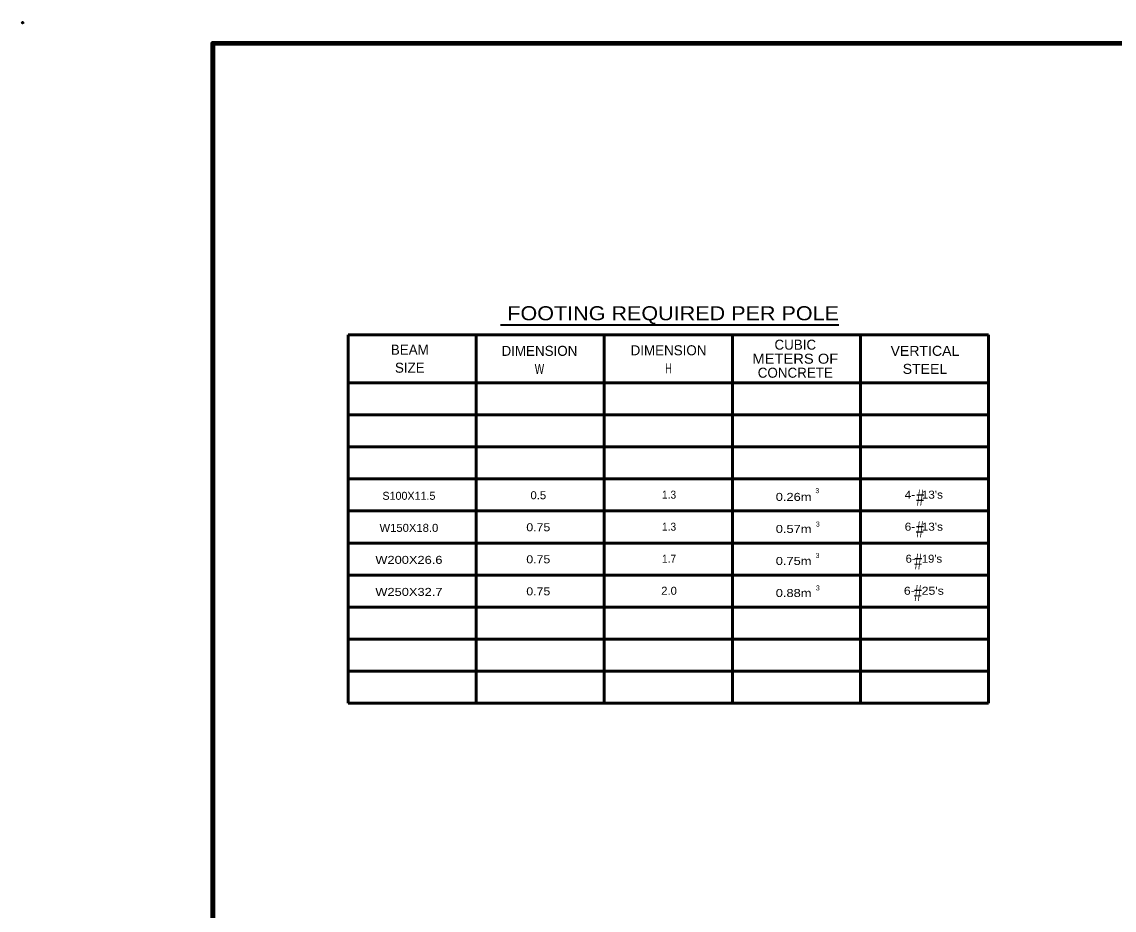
# Model space of a CAD drawing. Extents: x -27 to 828, y -12 to 532.
# Drawn here: x -27 to 300.5, y 265.3 to 531.5 of the extents above; entities that cross this region are included whole.
import ezdxf
from ezdxf.enums import TextEntityAlignment as Align

# ---------------------------------------------------------------- set-up
doc = ezdxf.new("R2010")
doc.units = 0
doc.header["$LTSCALE"] = 0.96
doc.header["$PDMODE"] = 32
doc.header["$PDSIZE"] = 0.48
doc.layers.add('1', color=7, linetype='Continuous', lineweight=35)

msp = doc.modelspace()

# ---------------------------------------------------------------- linework, layer by layer
at = {"layer": '1', "lineweight": 40}
msp.add_line((116.4853, 440.7034), (217.898, 440.7034), dxfattribs=at)
at = {"layer": '1', "lineweight": 53}
for p, q in [((70.8201, 437.7165), (262.8201, 437.7165)), ((70.8201, 437.7165), (70.8201, 327.3165)), ((109.2201, 437.7165), (109.2201, 327.3165)), ((147.6201, 437.7165), (147.6201, 327.3165)), ((186.0201, 437.7165), (186.0201, 327.3165)), ((224.4201, 437.7165), (224.4201, 327.3165)), ((262.8201, 437.7165), (262.8201, 327.3165)), ((70.8201, 423.3165), (262.8201, 423.3165)), ((70.8201, 413.7165), (262.8201, 413.7165)), ((70.8201, 404.1165), (262.8201, 404.1165)), ((70.8201, 394.5165), (262.8201, 394.5165)), ((70.8201, 384.9165), (262.8201, 384.9165)), ((70.8201, 375.3165), (262.8201, 375.3165)), ((70.8201, 365.7165), (262.8201, 365.7165)), ((70.8201, 356.1165), (262.8201, 356.1165)), ((70.8201, 346.5165), (262.8201, 346.5165)), ((70.8201, 336.9165), (262.8201, 336.9165)), ((70.8201, 327.3165), (262.8201, 327.3165))]:
    msp.add_line(p, q, dxfattribs=at)
at = {"layer": '1', "lineweight": 158}
msp.add_lwpolyline([(821.9567, 525.1688), (30.2567, 525.0688), (30.3567, -0.9312)], dxfattribs=at)
at = {"layer": '1'}
msp.add_point((-26.7433, 531.2688), dxfattribs=at)

# ---------------------------------------------------------------- texts
for s, height, width, p in [('FOOTING REQUIRED PER POLE', 4.2, 1.15, (118.549, 442.0796)), ('#', 4.8, 0.65, (241.1377, 386.5205)), ('#', 4.8, 0.65, (241.0754, 377.0515)), ('#', 4.8, 0.65, (240.5657, 367.3979)), ('#', 4.8, 0.65, (240.4411, 357.9289))]:
    msp.add_text(s, height=height, dxfattribs=dict(at, width=width)).set_placement(p)
for s, height, p in [('CUBIC', 3, (204.8785, 433.2538)), ('BEAM', 3, (89.3139, 431.7538)), ('DIMENSION', 3, (128.1793, 431.4098)), ('DIMENSION', 3, (166.8728, 431.5818)), ('SIZE', 3, (89.314, 426.3538)), ('CONCRETE', 3, (204.8785, 424.8538)), ('S100X11.5', 2.4, (89.0517, 388.2656))]:
    msp.add_text(s, height=height, dxfattribs=at).set_placement(p, align=Align.CENTER)
for s, height, width, p in [('VERTICAL', 3, 1.05, (243.7439, 431.4098)), ('W', 3, 0.75, (128.1795, 426.0098)), ('H', 3, 0.7, (166.873, 426.1818)), ('METERS OF', 3, 1.1, (204.8786, 429.0538)), ('STEEL', 3, 1.05, (243.744, 426.0098)), ('0.5', 2.4, 1.05, (127.8354, 388.4376)), ('1.3', 2.4, 0.95, (167.0363, 388.6096)), ('0.26m', 2.4, 1.2, (204.3711, 387.9386)), ('3', 1.5, 0.9, (211.4686, 390.2609)), ("4-  13's", 2.4, 1.1, (243.4086, 388.6096)), ('W150X18.0', 2.4, 1.05, (89.0517, 378.6656)), ('0.75', 2.4, 1.15, (127.8355, 378.8376)), ('1.3', 2.4, 0.95, (167.0363, 379.0096)), ('0.57m', 2.4, 1.2, (204.371, 378.3386)), ('3', 1.5, 0.9, (211.6192, 380.2435)), ("6-  13's", 2.4, 1.1, (243.4086, 379.0096)), ('W200X26.6', 2.4, 1.2, (89.0517, 369.0656)), ('0.75', 2.4, 1.15, (127.8355, 369.2376)), ('1.7', 2.4, 0.95, (167.0364, 369.4096)), ('0.75m', 2.4, 1.2, (204.371, 368.7386)), ('3', 1.5, 0.9, (211.5439, 370.8287)), ("6-  19's", 2.4, 1.05, (243.4085, 369.4096)), ('W250X32.7', 2.4, 1.2, (89.0517, 359.4656)), ('0.75', 2.4, 1.15, (127.8355, 359.6376)), ('2.0', 2.4, 1.05, (167.0363, 359.8096)), ('0.88m', 2.4, 1.2, (204.3711, 359.1386)), ('3', 1.5, 0.9, (211.6192, 361.1126)), ("6-  25's", 2.4, 1.15, (243.4085, 359.8096))]:
    msp.add_text(s, height=height, dxfattribs=dict(at, width=width)).set_placement(p, align=Align.CENTER)

doc.saveas('drawing.dxf')
